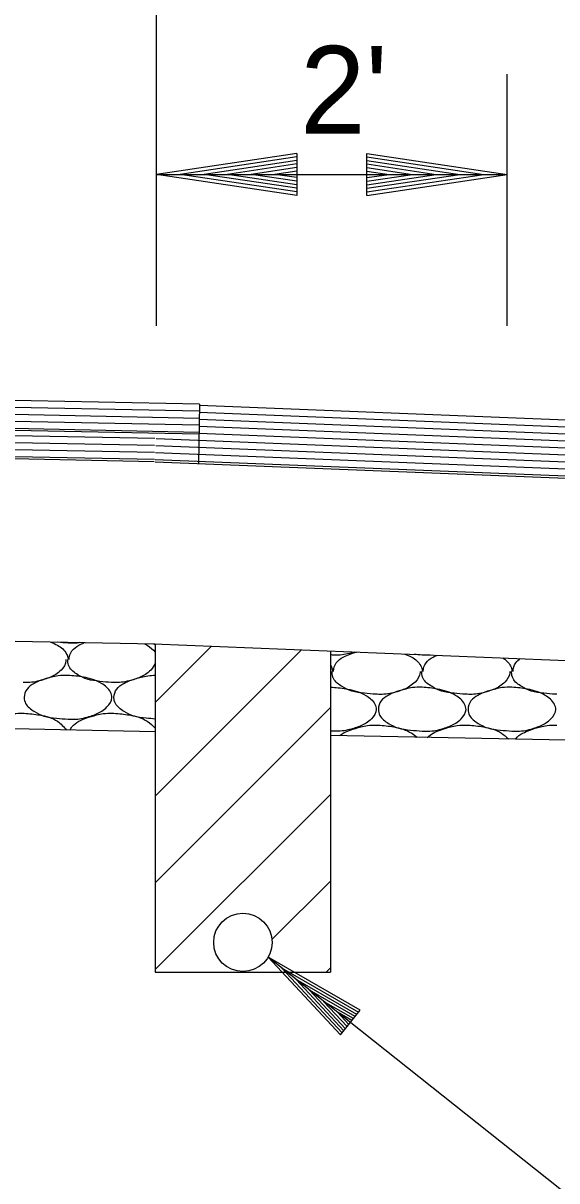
# Model space of a CAD drawing. Extents: x 1364961 to 1365294, y 367927 to 368034.
# Drawn here: x 1365055.22 to 1365058.27, y 367994.9 to 368001.5 of the extents above; entities that cross this region are included whole.
import ezdxf

# ---------------------------------------------------------------- set-up
doc = ezdxf.new("R2010")
doc.units = 0
doc.layers.add('Default', color=7, linetype='Continuous')

msp = doc.modelspace()

# ---------------------------------------------------------------- linework, layer by layer
at = {"layer": 'Default'}
for p, q in [((1365055.9832, 367999.7767), (1365055.9832, 368003.9983)), ((1365057.9832, 367999.7767), (1365057.9832, 368001.2128)), ((1365056.7832, 368000.7611), (1365055.9832, 368000.6411)), ((1365056.7832, 368000.7411), (1365056.1168, 368000.6411)), ((1365056.7832, 368000.7207), (1365056.2544, 368000.6411)), ((1365056.7832, 368000.7611), (1365056.7832, 368000.5211)), ((1365057.1832, 368000.7611), (1365057.9832, 368000.6411)), ((1365057.1832, 368000.5211), (1365057.1832, 368000.7611)), ((1365057.1832, 368000.7411), (1365057.8496, 368000.6411)), ((1365057.1832, 368000.7207), (1365057.712, 368000.6411)), ((1365056.7832, 368000.7007), (1365056.3876, 368000.6411)), ((1365056.7832, 368000.6799), (1365056.5232, 368000.6411)), ((1365056.7832, 368000.6599), (1365056.6568, 368000.6411)), ((1365057.1832, 368000.7007), (1365057.5788, 368000.6411)), ((1365057.1832, 368000.6803), (1365057.4432, 368000.6411)), ((1365057.1832, 368000.6599), (1365057.3096, 368000.6411)), ((1365055.9832, 368000.6411), (1365057.9832, 368000.6411)), ((1365056.7832, 368000.5211), (1365055.9832, 368000.6411)), ((1365056.7832, 368000.5411), (1365056.1168, 368000.6411)), ((1365056.7832, 368000.5615), (1365056.2544, 368000.6411)), ((1365056.7832, 368000.5815), (1365056.3876, 368000.6411)), ((1365056.7832, 368000.6019), (1365056.5232, 368000.6411)), ((1365056.7832, 368000.6223), (1365056.6568, 368000.6411)), ((1365057.1832, 368000.5211), (1365057.9832, 368000.6411)), ((1365057.1832, 368000.6023), (1365057.4432, 368000.6411)), ((1365057.1832, 368000.5615), (1365057.712, 368000.6411)), ((1365057.1832, 368000.5411), (1365057.8496, 368000.6411)), ((1365057.1832, 368000.5815), (1365057.5788, 368000.6411)), ((1365057.1832, 368000.6223), (1365057.3096, 368000.6411)), ((1365056.2272, 367999.3287), (1365031.9943, 367999.8127)), ((1365056.2264, 367999.2887), (1365031.9953, 367999.7727)), ((1365056.2256, 367999.2487), (1365031.9953, 367999.7327)), ((1365056.2248, 367999.2088), (1365031.9973, 367999.6927)), ((1365056.2238, 367999.1588), (1365031.7475, 367999.6476)), ((1365056.224, 367999.1687), (1365031.9973, 367999.6527)), ((1365055.9732, 367999.1337), (1365031.9983, 367999.6127)), ((1365055.9722, 367999.0937), (1365031.9993, 367999.5727)), ((1365055.9712, 367999.0537), (1365031.9993, 367999.5327)), ((1365055.9702, 367999.0007), (1365031.9943, 367999.4797)), ((1365055.9712, 367999.0137), (1365032.0013, 367999.4927)), ((1365056.2272, 367999.3287), (1365056.222, 367998.9909)), ((1365056.2263, 367999.2842), (1365066.0082, 367998.8937)), ((1365056.2271, 367999.3242), (1365065.9662, 367998.9357)), ((1365056.2247, 367999.2041), (1365066.0912, 367998.8107)), ((1365056.2255, 367999.2442), (1365066.0492, 367998.8527)), ((1365055.9802, 367999.1337), (1365066.1752, 367998.7267)), ((1365056.2239, 367999.1641), (1365066.1332, 367998.7687)), ((1365055.9782, 367999.0937), (1365066.2162, 367998.6857)), ((1365055.9752, 367999.0137), (1365066.3002, 367998.6017)), ((1365055.9752, 367999.0007), (1365066.3142, 367998.5877)), ((1365055.9772, 367999.0537), (1365066.2582, 367998.6437)), ((1365055.9752, 367997.9597), (1365031.9883, 367998.4397)), ((1365055.9672, 367997.9617), (1365059.4142, 367997.8227)), ((1365055.9672, 367997.9607), (1365055.9752, 367997.9607)), ((1365055.9752, 367997.9607), (1365055.9752, 367996.0877)), ((1365055.9752, 367997.6267), (1365056.2972, 367997.9487)), ((1365055.9752, 367997.4597), (1365031.9783, 367997.9397)), ((1365055.9752, 367997.0927), (1365056.8102, 367997.9277)), ((1365056.9752, 367997.9207), (1365056.9752, 367996.0877)), ((1365056.9752, 367997.7147), (1365056.9862, 367997.7137)), ((1365055.2222, 367997.5657), (1365055.2282, 367997.5657)), ((1365055.7342, 367997.5657), (1365055.7402, 367997.5657)), ((1365055.9752, 367996.5977), (1365056.9752, 367997.5977)), ((1365055.9752, 367997.5877), (1365055.9752, 367997.5877)), ((1365057.2422, 367997.4977), (1365057.2482, 367997.4977)), ((1365057.7542, 367997.4977), (1365057.7602, 367997.4977)), ((1365077.4832, 367997.0287), (1365056.9752, 367997.4387)), ((1365055.9752, 367996.1027), (1365056.9752, 367997.1027)), ((1365056.6412, 367996.2737), (1365056.9752, 367996.6077)), ((1365058.7765, 367994.4605), (1365056.6189, 367996.173)), ((1365057.0324, 367995.7294), (1365056.6189, 367996.173)), ((1365057.1446, 367995.8705), (1365056.6189, 367996.173)), ((1365057.0421, 367995.7416), (1365056.6977, 367996.1112)), ((1365057.1359, 367995.8583), (1365056.6977, 367996.1112)), ((1365056.9502, 367996.0877), (1365056.9752, 367996.1127)), ((1365055.9752, 367996.0877), (1365056.9752, 367996.0877)), ((1365057.1262, 367995.847), (1365056.7785, 367996.0464)), ((1365057.0518, 367995.7529), (1365056.7785, 367996.0464)), ((1365057.0615, 367995.7652), (1365056.8563, 367995.9845)), ((1365057.1165, 367995.8347), (1365056.8563, 367995.9845)), ((1365057.1068, 367995.8235), (1365056.9361, 367995.9207)), ((1365057.0711, 367995.7775), (1365056.9361, 367995.9207)), ((1365057.0972, 367995.8112), (1365057.0148, 367995.8589)), ((1365057.0798, 367995.7887), (1365057.0148, 367995.8589)), ((1365057.0324, 367995.7294), (1365057.1446, 367995.8705))]:
    msp.add_line(p, q, dxfattribs=at)
msp.add_circle((1365056.4757, 367996.2581), 0.1667, dxfattribs=at)
for points in [[(1365055.3792, 367997.9717), (1365055.4182, 367997.9537), (1365055.4702, 367997.9037), (1365055.4782, 367997.8737), (1365055.4782, 367997.8717)], [(1365055.5462, 367997.9687), (1365055.5222, 367997.9657), (1365055.4782, 367997.9657), (1365055.4202, 367997.9707)], [(1365055.4842, 367997.8717), (1365055.4842, 367997.8737), (1365055.5002, 367997.9217), (1365055.5402, 367997.9537), (1365055.5702, 367997.9677)], [(1365055.9162, 367997.9607), (1365055.9302, 367997.9537), (1365055.9752, 367997.9147)], [(1365057.1142, 367997.9147), (1365057.0302, 367997.8977), (1365056.9862, 367997.8977), (1365056.9752, 367997.8987)], [(1365056.9922, 367997.8037), (1365056.9922, 367997.8057), (1365057.0082, 367997.8537), (1365057.0482, 367997.8857), (1365057.0882, 367997.9037), (1365057.1232, 367997.9147)], [(1365057.3992, 367997.9037), (1365057.4382, 367997.8857), (1365057.4902, 367997.8357), (1365057.4982, 367997.8057), (1365057.4982, 367997.8037)], [(1365057.5442, 367997.8977), (1365057.5422, 367997.8977), (1365057.4982, 367997.8977), (1365057.4532, 367997.9017)], [(1365057.5042, 367997.8037), (1365057.5042, 367997.8057), (1365057.5202, 367997.8537), (1365057.5602, 367997.8857), (1365057.5822, 367997.8967)], [(1365057.9582, 367997.8817), (1365058.0022, 367997.8357), (1365058.0102, 367997.8057), (1365058.0102, 367997.8037)], [(1365058.0162, 367997.8037), (1365058.0162, 367997.8057), (1365058.0322, 367997.8537), (1365058.0572, 367997.8777)], [(1365055.4662, 367997.8717), (1365055.4662, 367997.8657), (1365055.4382, 367997.8117), (1365055.4082, 367997.7877), (1365055.3462, 367997.7597), (1365055.2602, 367997.7417), (1365055.2222, 367997.7417)], [(1365055.7342, 367997.7417), (1365055.7262, 367997.7417), (1365055.6602, 367997.7477), (1365055.5882, 367997.7597), (1365055.5342, 367997.7857), (1365055.4842, 367997.8317), (1365055.4762, 367997.8657), (1365055.4762, 367997.8717)], [(1365055.9752, 367997.8497), (1365055.9502, 367997.8117), (1365055.9202, 367997.7877), (1365055.8582, 367997.7597), (1365055.7722, 367997.7417), (1365055.7342, 367997.7417)], [(1365056.9752, 367997.8407), (1365056.9782, 367997.8357), (1365056.9862, 367997.8057), (1365056.9862, 367997.8037)], [(1365055.4782, 367997.7817), (1365055.5662, 367997.7717), (1365055.6682, 367997.7357), (1365055.7202, 367997.6857), (1365055.7282, 367997.6557), (1365055.7002, 367997.6017), (1365055.6702, 367997.5777), (1365055.6082, 367997.5497), (1365055.5222, 367997.5317), (1365055.4782, 367997.5317), (1365055.4122, 367997.5377), (1365055.3402, 367997.5497), (1365055.2862, 367997.5757), (1365055.2362, 367997.6217), (1365055.2282, 367997.6557), (1365055.2442, 367997.7037), (1365055.2842, 367997.7357), (1365055.3242, 367997.7537), (1365055.3842, 367997.7717), (1365055.4222, 367997.7797), (1365055.4782, 367997.7817)], [(1365055.9752, 367997.5327), (1365055.9242, 367997.5377), (1365055.8522, 367997.5497), (1365055.7982, 367997.5757), (1365055.7482, 367997.6217), (1365055.7402, 367997.6557), (1365055.7562, 367997.7037), (1365055.7962, 367997.7357), (1365055.8362, 367997.7537), (1365055.8962, 367997.7717), (1365055.9342, 367997.7797), (1365055.9752, 367997.7827)], [(1365057.2422, 367997.6737), (1365057.2342, 367997.6737), (1365057.1682, 367997.6797), (1365057.0962, 367997.6917), (1365057.0422, 367997.7177), (1365056.9922, 367997.7637), (1365056.9842, 367997.7977), (1365056.9842, 367997.8037)], [(1365057.4862, 367997.8037), (1365057.4862, 367997.7977), (1365057.4582, 367997.7437), (1365057.4282, 367997.7197), (1365057.3662, 367997.6917), (1365057.2802, 367997.6737), (1365057.2422, 367997.6737)], [(1365057.7542, 367997.6737), (1365057.7462, 367997.6737), (1365057.6802, 367997.6797), (1365057.6082, 367997.6917), (1365057.5542, 367997.7177), (1365057.5042, 367997.7637), (1365057.4962, 367997.7977), (1365057.4962, 367997.8037)], [(1365057.9982, 367997.8037), (1365057.9982, 367997.7977), (1365057.9702, 367997.7437), (1365057.9402, 367997.7197), (1365057.8782, 367997.6917), (1365057.7922, 367997.6737), (1365057.7542, 367997.6737)], [(1365058.2662, 367997.6737), (1365058.2582, 367997.6737), (1365058.1922, 367997.6797), (1365058.1202, 367997.6917), (1365058.0662, 367997.7177), (1365058.0162, 367997.7637), (1365058.0082, 367997.7977), (1365058.0082, 367997.8037)], [(1365056.9862, 367997.7137), (1365057.0742, 367997.7037), (1365057.1762, 367997.6677), (1365057.2282, 367997.6177), (1365057.2362, 367997.5877), (1365057.2082, 367997.5337), (1365057.1782, 367997.5097), (1365057.1162, 367997.4817), (1365057.0302, 367997.4637), (1365056.9862, 367997.4637), (1365056.9752, 367997.4647)], [(1365057.4982, 367997.7137), (1365057.5862, 367997.7037), (1365057.6882, 367997.6677), (1365057.7402, 367997.6177), (1365057.7482, 367997.5877), (1365057.7202, 367997.5337), (1365057.6902, 367997.5097), (1365057.6282, 367997.4817), (1365057.5422, 367997.4637), (1365057.4982, 367997.4637), (1365057.4322, 367997.4697), (1365057.3602, 367997.4817), (1365057.3062, 367997.5077), (1365057.2562, 367997.5537), (1365057.2482, 367997.5877), (1365057.2642, 367997.6357), (1365057.3042, 367997.6677), (1365057.3442, 367997.6857), (1365057.4042, 367997.7037), (1365057.4422, 367997.7117), (1365057.4982, 367997.7137)], [(1365058.0102, 367997.7137), (1365058.0982, 367997.7037), (1365058.2002, 367997.6677), (1365058.2522, 367997.6177), (1365058.2602, 367997.5877), (1365058.2322, 367997.5337), (1365058.2022, 367997.5097), (1365058.1402, 367997.4817), (1365058.0542, 367997.4637), (1365058.0102, 367997.4637), (1365057.9442, 367997.4697), (1365057.8722, 367997.4817), (1365057.8182, 367997.5077), (1365057.7682, 367997.5537), (1365057.7602, 367997.5877), (1365057.7762, 367997.6357), (1365057.8162, 367997.6677), (1365057.8562, 367997.6857), (1365057.9162, 367997.7037), (1365057.9542, 367997.7117), (1365058.0102, 367997.7137)], [(1365054.9832, 367997.4797), (1365054.9882, 367997.4877), (1365055.0282, 367997.5197), (1365055.0682, 367997.5377), (1365055.1282, 367997.5557), (1365055.1662, 367997.5637), (1365055.2222, 367997.5657)], [(1365055.2282, 367997.5657), (1365055.3162, 367997.5557), (1365055.4182, 367997.5197), (1365055.4702, 367997.4697)], [(1365055.4902, 367997.4697), (1365055.5002, 367997.4877), (1365055.5402, 367997.5197), (1365055.5802, 367997.5377), (1365055.6402, 367997.5557), (1365055.6782, 367997.5637), (1365055.7342, 367997.5657)], [(1365055.7402, 367997.5657), (1365055.8282, 367997.5557), (1365055.9302, 367997.5197), (1365055.9752, 367997.4807)], [(1365057.0252, 367997.4377), (1365057.0482, 367997.4517), (1365057.0882, 367997.4697), (1365057.1482, 367997.4877), (1365057.1862, 367997.4957), (1365057.2422, 367997.4977)], [(1365057.2482, 367997.4977), (1365057.3362, 367997.4877), (1365057.4382, 367997.4517), (1365057.4702, 367997.4287)], [(1365057.5272, 367997.4277), (1365057.5602, 367997.4517), (1365057.6002, 367997.4697), (1365057.6602, 367997.4877), (1365057.6982, 367997.4957), (1365057.7542, 367997.4977)], [(1365057.7602, 367997.4977), (1365057.8482, 367997.4877), (1365057.9502, 367997.4517), (1365057.9912, 367997.4187)], [(1365058.0312, 367997.4177), (1365058.0322, 367997.4197), (1365058.0722, 367997.4517), (1365058.1122, 367997.4697), (1365058.1722, 367997.4877), (1365058.2102, 367997.4957), (1365058.2662, 367997.4977)]]:
    msp.add_spline(points, degree=3, dxfattribs=at)

# ---------------------------------------------------------------- texts
msp.add_text("2'", height=0.5, dxfattribs=at).set_placement((1365056.8025, 368000.8741))

doc.saveas('drawing.dxf')
